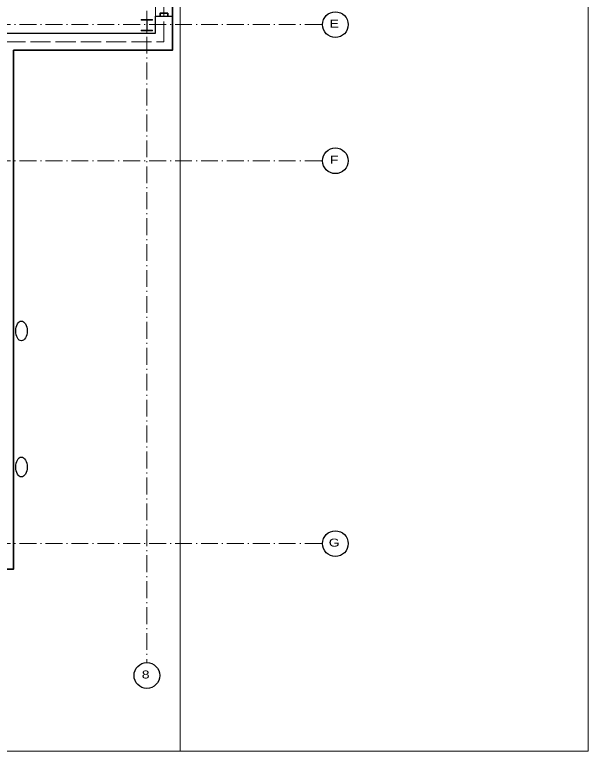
# Model space of a CAD drawing. Extents: x -118748 to -117136, y -118748 to -117596.
# Drawn here: x -117459.3 to -117135.6, y -118748.4 to -118332.8 of the extents above; entities that cross this region are included whole.
import ezdxf
from ezdxf.enums import TextEntityAlignment as Align

# ---------------------------------------------------------------- set-up
doc = ezdxf.new("R2010")
doc.units = 0
doc.header["$LTSCALE"] = 1.9
doc.linetypes.add('DOT_DASHED', pattern=[7.7, 5, -1.2, 0.3, -1.2])
doc.linetypes.add('LONG_DASHED', pattern=[7.5, 6, -1.5])
for name, color, linetype, lineweight in [('10', 7, 'DOT_DASHED', 13), ('11', 7, 'Continuous', 25), ('12', 7, 'Continuous', 13), ('15', 7, 'Continuous', 13), ('16', 7, 'Continuous', 13), ('2', 7, 'Continuous', 35), ('3', 7, 'Continuous', 35), ('43', 7, 'Continuous', 25), ('60', 7, 'LONG_DASHED', 13)]:
    doc.layers.add(name, color=color, linetype=linetype, lineweight=lineweight)

msp = doc.modelspace()

# ---------------------------------------------------------------- linework, layer by layer
at = {"layer": '10'}
for p, q in [((-117384.721, -117628.339), (-117384.721, -118698.41)), ((-118641.571, -118338.41), (-117285.521, -118338.41)), ((-118641.571, -118415.21), (-117285.521, -118415.21)), ((-118641.571, -118631.21), (-117285.521, -118631.21))]:
    msp.add_line(p, q, dxfattribs=at)
at = {"layer": '11'}
for centre in [(-117278.321, -118338.41), (-117278.321, -118415.21), (-117278.321, -118631.21), (-117384.721, -118705.61)]:
    msp.add_circle(centre, 7.253, dxfattribs=at)
at = {"layer": '12'}
msp.add_lwpolyline([(-117387.904, -118341.962), (-117381.488, -118341.962), (-117381.488, -118341.566), (-117384.572, -118341.566), (-117384.572, -118335.862), (-117381.488, -118335.862), (-117381.488, -118335.466), (-117387.904, -118335.466), (-117387.904, -118335.862), (-117384.82, -118335.862), (-117384.82, -118341.566), (-117387.904, -118341.566)], close=True, dxfattribs=at)
at = {"layer": '15', "lineweight": 25}
for p, q in [((-117379.921, -118333.61), (-117370.321, -118333.61)), ((-117379.921, -118343.21), (-117379.921, -118333.61)), ((-117370.321, -118352.81), (-117370.321, -118333.61)), ((-117469.521, -118343.21), (-117379.921, -118343.21)), ((-117459.921, -118352.81), (-117370.321, -118352.81))]:
    msp.add_line(p, q, dxfattribs=at)
at = {"layer": '16'}
for p, q in [((-117379.921, -118333.61), (-117379.921, -118295.21)), ((-117370.321, -118295.21), (-117370.321, -118333.61))]:
    msp.add_line(p, q, dxfattribs=at)
at = {"layer": '16', "lineweight": 35}
msp.add_lwpolyline([(-117377.303, -118333.61), (-117377.303, -118332.01), (-117372.939, -118332.01), (-117372.939, -118333.61)], dxfattribs=at)
at = {"layer": '2', "lineweight": 13}
msp.add_lwpolyline([(-118748.365, -118748.365), (-117365.965, -118748.365), (-117365.965, -117826.765), (-118748.365, -117826.765), (-118748.365, -118748.365), (-117135.565, -118748.365), (-117135.565, -117596.365), (-118748.365, -117596.365)], close=True, dxfattribs=at)
at = {"layer": '3'}
msp.add_lwpolyline([(-118098.321, -117954.41), (-117829.521, -117954.41), (-117459.921, -117954.41), (-117459.921, -118170.41), (-117370.321, -118170.41), (-117370.321, -118352.81), (-117459.921, -118352.81), (-117459.921, -118645.61), (-117704.721, -118645.61), (-117704.721, -118592.81), (-117847.121, -118592.81), (-117850.321, -118592.801), (-117860.744, -118590.984), (-117862.249, -118590.443), (-117871.571, -118585.668), (-117872.847, -118584.703), (-117880.323, -118577.368), (-117881.254, -118576.067), (-117886.205, -118566.837), (-117886.706, -118565.318), (-117888.682, -118555.032), (-117888.707, -118553.433), (-117890.316, -118553.433)], dxfattribs=at)
at = {"layer": '43'}
for centre in [(-117455.521, -118511.21), (-117455.521, -118588.01)]:
    msp.add_ellipse(centre, major_axis=(0, -5.6), ratio=0.571429, dxfattribs=at)
at = {"layer": '60'}
for points in [[(-117375.121, -118348.01), (-117375.121, -118175.21), (-117464.721, -118175.21)], [(-117464.721, -118640.81), (-117464.721, -118348.01), (-117375.121, -118348.01)]]:
    msp.add_lwpolyline(points, dxfattribs=at)

# ---------------------------------------------------------------- texts
at = {"layer": '11', "width": 1.3}
for s, p in [(' E ', (-117279.001, -118340.11)), (' F ', (-117279.001, -118416.91)), (' G ', (-117279.001, -118632.91)), (' 8 ', (-117385.401, -118707.31))]:
    msp.add_text(s, height=4.518, dxfattribs=at).set_placement(p, align=Align.CENTER)

doc.saveas('drawing.dxf')
